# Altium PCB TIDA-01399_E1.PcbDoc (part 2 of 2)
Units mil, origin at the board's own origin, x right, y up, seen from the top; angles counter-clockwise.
Board outline 5937.01 x 6299.21 mil, 4 copper layers (Top Layer, MidLayer1, MidLayer2, Bottom Layer), stack 61.2 mil thick; 192 components, 137 nets, 411 pads, 57 vias.
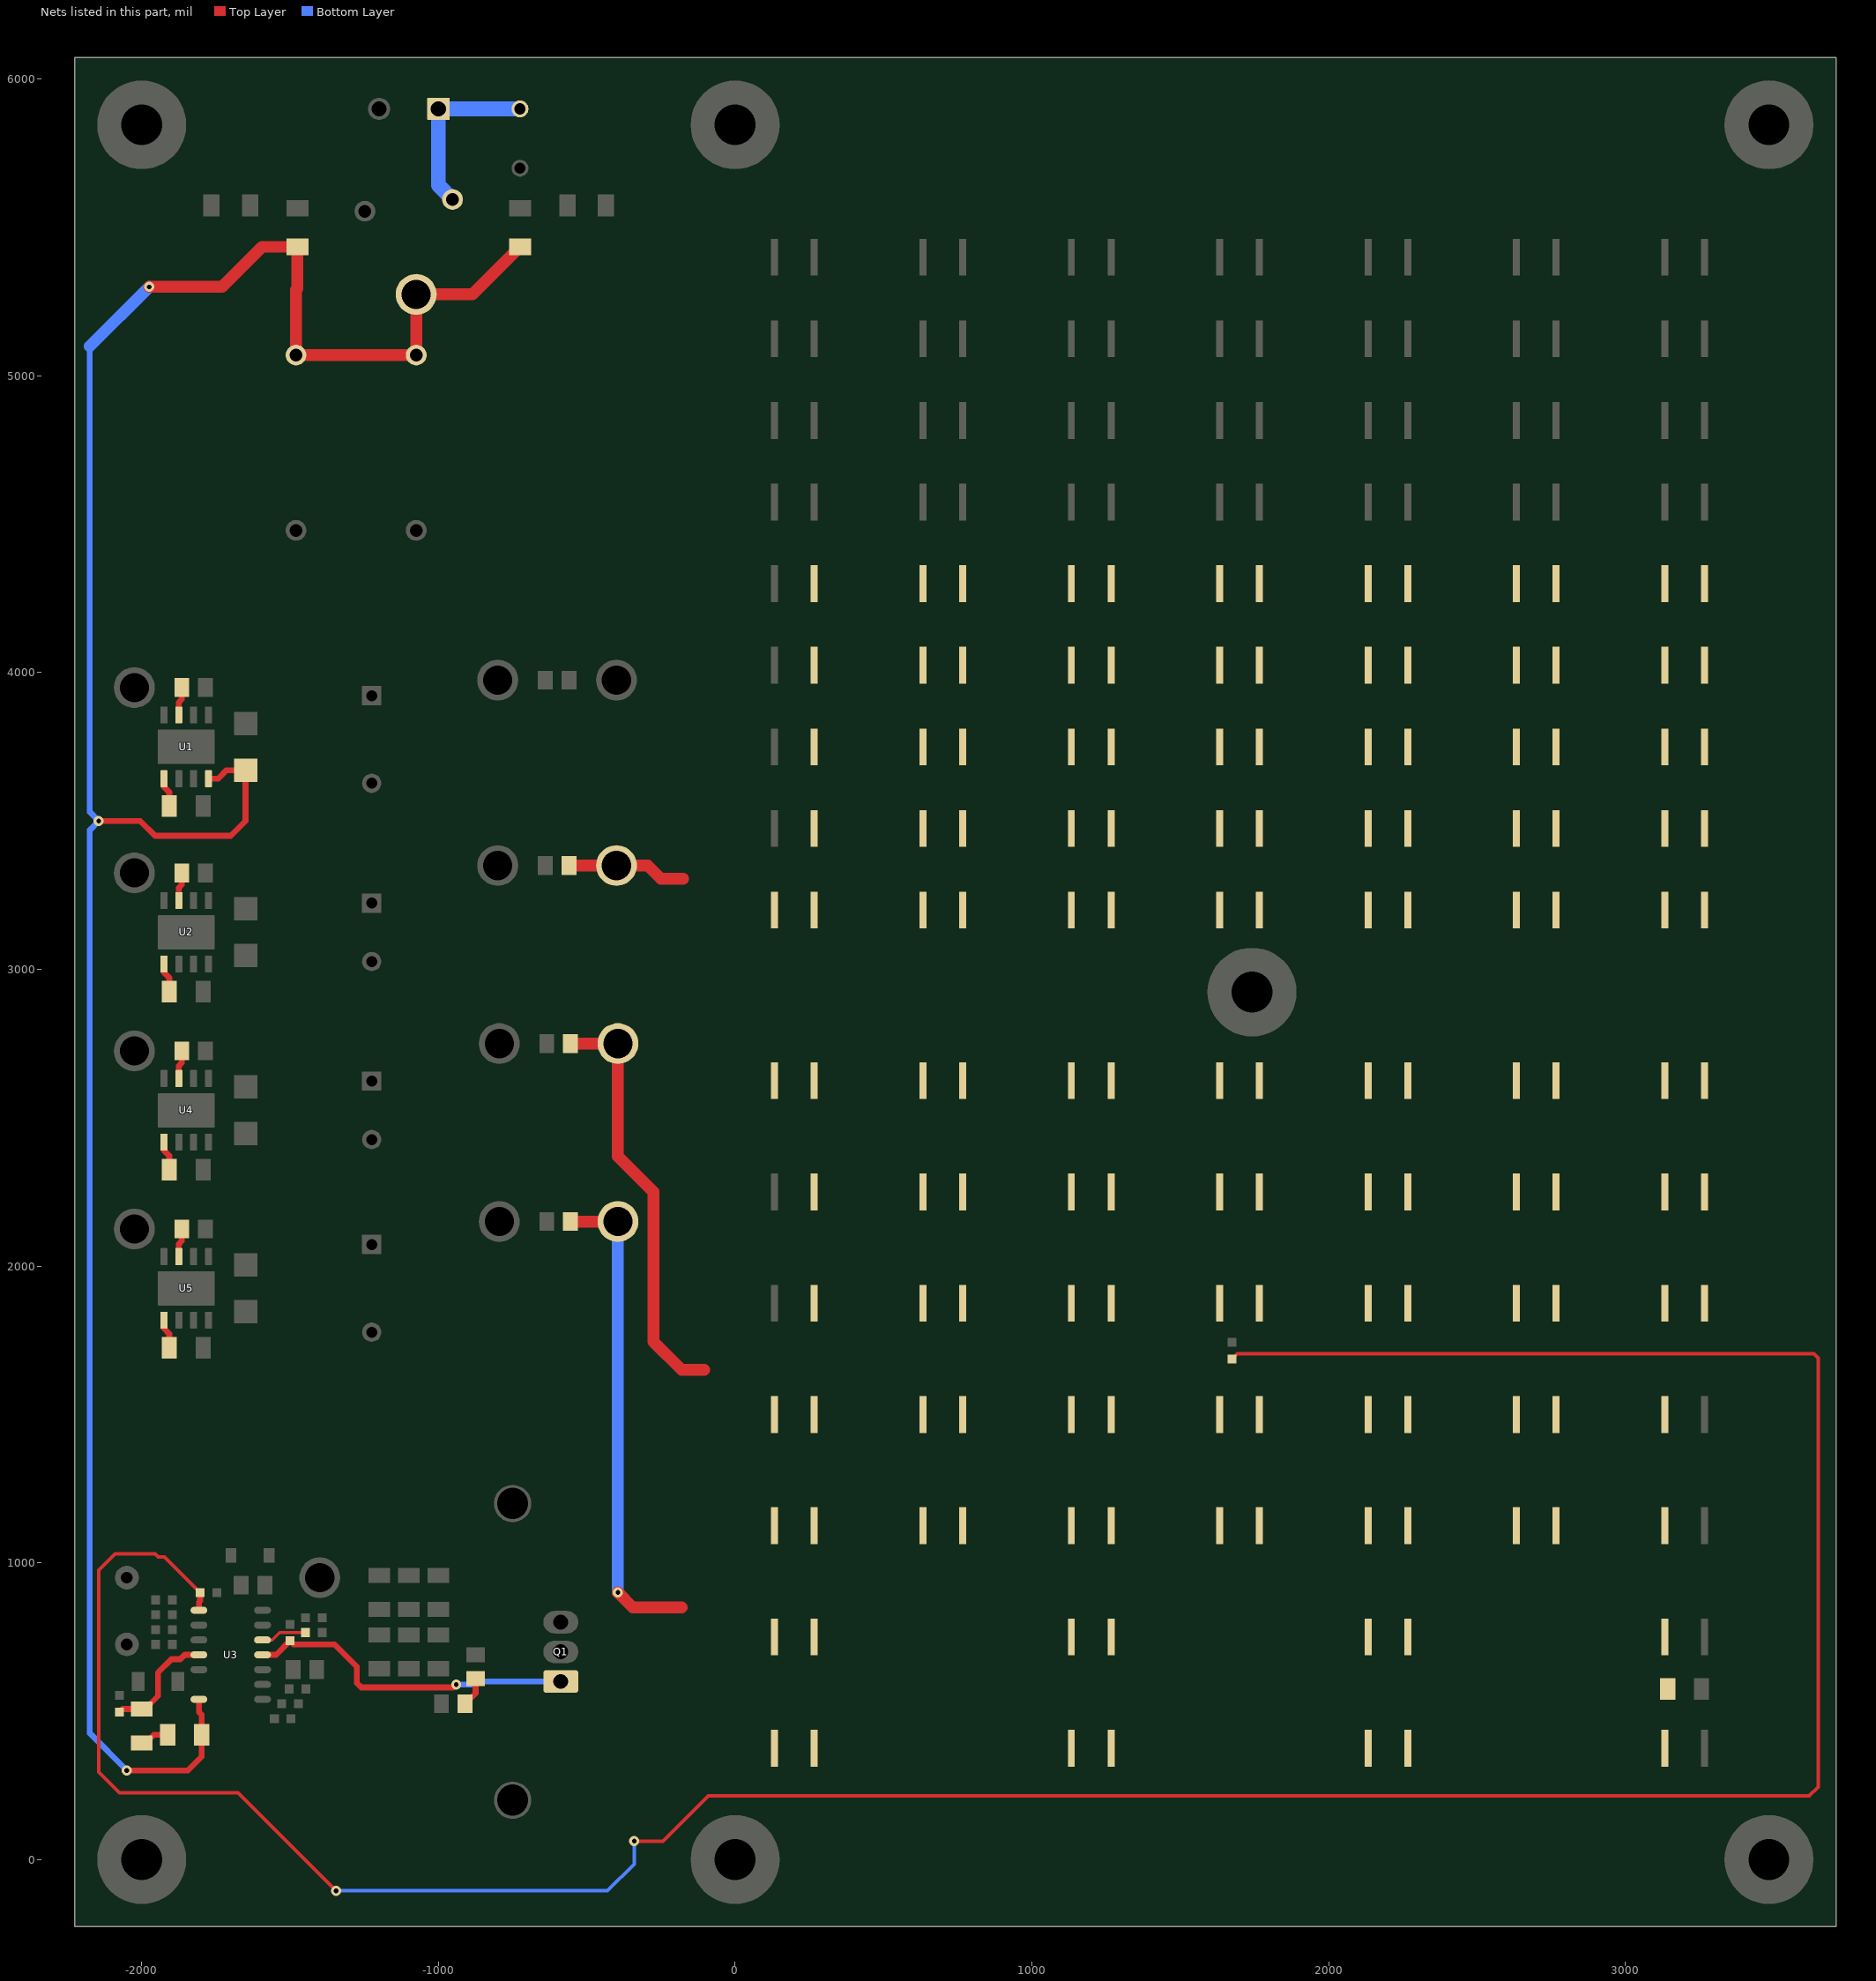
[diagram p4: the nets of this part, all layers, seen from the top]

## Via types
v1: diameter 34, hole 16, Top Layer to Bottom Layer, 25 vias
v2: diameter 19.68, hole 7.87, Top Layer to Bottom Layer, tented both sides, 16 vias
v3: diameter 19.68, hole 7.87, Top Layer to Bottom Layer, 16 vias

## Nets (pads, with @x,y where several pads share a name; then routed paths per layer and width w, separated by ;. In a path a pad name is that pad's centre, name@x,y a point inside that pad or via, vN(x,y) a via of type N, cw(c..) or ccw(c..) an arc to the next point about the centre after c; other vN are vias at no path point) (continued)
NetD32_2: D32.2 D33.1
NetD33_2: D33.2 D34.1
NetD34_2: D34.2 D35.1
NetD35_2: D35.2 D36.1
NetD36_2: D36.2 D37.1
NetD37_2: D37.2 D38.1
NetD38_2: D38.2 D61.1
NetD39_2: D39.2 D40.1
NetD40_2: D40.2 D41.1
NetD41_2: D41.2 D42.1
NetD42_2: D42.2 D43.1
NetD43_2: D43.2 D44.1
NetD44_2: D44.2 D45.1
NetD45_2: D45.2 D54.1
NetD48_1: D48.1 D49.2
NetD49_1: D49.1 D50.2
NetD50_1: D50.1 D51.2
NetD51_1: D51.1 D52.2
NetD52_1: D52.1 D53.2
NetD53_1: D53.1 D54.2
NetD55_1: D55.1 D56.2
NetD56_1: D56.1 D57.2
NetD57_1: D57.1 D58.2
NetD58_1: D58.1 D59.2
NetD59_1: D59.1 D60.2
NetD60_1: D60.1 D61.2
NetD62_1: D62.1 D70.1 R8.2 TP5.1 | length 403.6
  Top Layer w40: R8.2@-560,3350 TP5.1@-400,3350 -295,3350 -250,3305 -175,3305
NetD62_2: D62.2 D63.1
NetD63_2: D63.2 D64.1
NetD64_2: D64.2 D65.1
NetD65_2: D65.2 D66.1
NetD66_2: D66.2 D67.1
NetD67_2: D67.2 D68.1
NetD68_2: D68.2 D90.1
NetD70_2: D70.2 D71.1
NetD71_2: D71.2 D72.1
NetD72_2: D72.2 D73.1
NetD73_2: D73.2 D74.1
NetD74_2: D74.2 D75.1
NetD75_2: D75.2 D76.1
NetD76_2: D76.2 D83.1
NetD77_1: D77.1 D78.2
NetD78_1: D78.1 D79.2
NetD79_1: D79.1 D80.2
NetD80_1: D80.1 D81.2
NetD81_1: D81.1 D82.2
NetD82_1: D82.1 D83.2
NetD84_1: D84.1 D85.2
NetD85_1: D85.1 D86.2
NetD86_1: D86.1 D87.2
NetD87_1: D87.1 D88.2
NetD88_1: D88.1 D89.2
NetD89_1: D89.1 D90.2
NetD91_1: D91.1 D99.1 R17.2 TP9.1 | length 1419.1
  Top Layer w40: R17.2@-555,2750 TP9.1@-395,2750 -395,2370 -275,2250 -275,1745 -180,1650 ; -175,1650 -105,1650
NetD91_2: D91.2 D92.1
NetD92_2: D92.2 D93.1
NetD93_2: D93.2 D94.1
NetD94_2: D94.2 D95.1
NetD95_2: D95.2 D96.1
NetD96_2: D96.2 D97.1
NetD99_2: D99.2 D100.1
NetD100_2: D100.2 D101.1
NetD101_2: D101.2 D102.1
NetD102_2: D102.2 D103.1
NetD103_2: D103.2 D104.1
NetD104_2: D104.2 D105.1
NetD107_1: D107.1 D110.1 R31.2 TP14.1 | length 1645.7
  Top Layer w40: R31.2@-555,2150 TP14.1@-395,2150 ; v1(-395,900) -345,850 -180,850
  Bottom Layer w40: v1(-395,900) TP14.1@-395,2150
NetD107_2: D107.2 D108.1
NetD108_2: D108.2 D113.1
NetD110_2: D110.2 D111.1
NetD111_2: D111.2 D112.1
NetD112_2: D112.2 D113.2 D114.1 D115.1 R34.2
NetF1_2: F1.2 J1.1 RV1.2 | length 600
  Bottom Layer w50: RV1.2@-952.36,5594.69 -1000,5642.32 J1.1@-1000,5900 F1.2@-725,5900
NetQ1_1: Q1.1 R16.2 U3.4 | length 1130.2
  Top Layer w20: U3.4@-1592.72,690 -1547,690 R16.2@-1500,737 -1488,725 -1350,725 -1275,650 -1275,595 -1260,580 -950,580 v1(-940,590)
  Bottom Layer w20: v1(-940,590) -890,590 -880,600 Q1.1@-587.5,600
NetR6_1: R6.1 U1.3 | length 96.9
  Top Layer w20: U1.3@-1875,3857.28 -1875,3900 -1865,3910 R6.1@-1865,3950
NetR7_2: R7.2 U1.5 | length 100.1
  Top Layer w20: U1.5@-1925,3642.72 -1925,3615 -1907.09,3597.09 R7.2@-1907.09,3550
NetR9_1: R9.1 U2.3 | length 96.9
  Top Layer w20: U2.3@-1875,3232.28 -1875,3275 -1865,3285 R9.1@-1865,3325
NetR10_2: R10.2 R14.2 | length 99.1
  Top Layer w20: R14.2@-2000,392.91 -1987.09,392.91 -1960,420 R10.2@-1912.09,420
NetR11_2: R11.2 R12.1 | length 99.5
  Top Layer w20: R11.2@-910,525 -875,560 R12.1@-875,610
NetR13_2: R13.2 U2.5 | length 100.1
  Top Layer w20: U2.5@-1925,3017.72 -1925,2990 -1907.09,2972.09 R13.2@-1907.09,2925
NetR14_1: R14.1 R23.2 U3.11 | length 393.8
  Top Layer w20: R23.2@-2075,497 -2064.91,507.09 R14.1@-2000,507.09 -1989.17,507.09 -1945,551.26 -1945,630 -1900,675 -1870,675 -1855,690 U3.11@-1807.28,690
NetR19_1: R19.1 RT1.2 U3.8 | length 10745
  Top Layer w12: R19.1@-1803,900 -1923,1020 -1945,1020 -1955,1030 -2090,1030 -2145,975 -2145,295 -2075,225 -1675,225 v1(-1345,-105) ; v1(-340,62.27) -242.73,62.27 -90,215 3620,215 3650,245 3650,1690 3635,1705 1693,1705 RT1.2@1675,1687
  Top Layer w20: U3.8@-1807.28,840 -1807.28,867.72 -1803,872 R19.1@-1803,900
  Bottom Layer w12: v1(-1345,-105) -430,-105 -340,-15 v1(-340,62.27)
NetR21_1: R21.1 U4.3 | length 96.9
  Top Layer w20: U4.3@-1875,2632.28 -1875,2675 -1865,2685 R21.1@-1865,2725
NetR26_2: R26.2 U4.5 | length 100.1
  Top Layer w20: U4.5@-1925,2417.72 -1925,2390 -1907.09,2372.09 R26.2@-1907.09,2325
NetR28_1: R28.1 U3.5 | length 155.1
  Top Layer w10: U3.5@-1592.72,740 -1560,740 -1535,765 R28.1@-1448,765
NetR32_1: R32.1 U5.3 | length 96.9
  Top Layer w20: U5.3@-1875,2032.28 -1875,2075 -1865,2085 R32.1@-1865,2125
NetR33_2: R33.2 U5.5 | length 100.1
  Top Layer w20: U5.5@-1925,1817.72 -1925,1790 -1907.09,1772.09 R33.2@-1907.09,1725
RECT-AC: C1.1 C3.1 D8.2 D16.1 D17.1 R10.1 RECT-AC1.1 U1.8 U3.14 | length 8421.1
  Top Layer w20: v1(-2145,3500) -2005,3500 -1955,3450 -1700,3450 -1650,3500 D8.2@-1650,3671.26 -1713.74,3671.26 -1742.28,3642.72 U1.8@-1775,3642.72 ; v1(-2050,300) -1845,300 -1797.91,347.09 R10.1@-1797.91,420 -1797.91,487.91 -1807.28,497.28 U3.14@-1807.28,540
  Top Layer w40: v1(-1975,5300) -1730,5300 -1594.96,5435.04 D17.1@-1475,5435.04 -1475,5295 -1480,5290 C1.1@-1480,5070.28 C3.1@-1075,5070.28 RECT-AC1.1@-1075,5275 -885.04,5275 D16.1@-725,5435.04
  Bottom Layer w20: -2175,5100 -2175,3530 v1(-2145,3500) -2175,3470 -2175,425 v1(-2050,300)
  Bottom Layer w40: -2175,5100 v1(-1975,5300)
pads on no net: H1.1 H1.2 H2.0 U1.2 U1.6 U1.7 U1.9@-1850,3750 U2.2 U2.6 U2.7 U2.9@-1850,3125 U4.2 U4.6 U4.7 U4.9@-1850,2525 U5.2 U5.6 U5.7 U5.9@-1850,1925

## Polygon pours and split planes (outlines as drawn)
NetC14_2 on MidLayer1 "NETC14_2_L02_P000" (solid, remove dead copper, pour order 0): -2150,2250 -1500,2250 -1100,1850 -900,1650 -900,1350 -900,1150 -850,1100 -750,1000 -600,1000 -450,850 -450,550 -550,450 -850,450 -1200,800 -1200,1300 -1450,1550 -1700,1550 -2050,1550 -2150,1650
NetC12_2 on MidLayer1 "NETC12_2_L02_P002" (solid, remove dead copper, pour order 2): -2150,2850 -1100,2850 -1100,2350 -2150,2350
NetC4_2 on MidLayer1 "NETC4_2_L02_P004" (solid, remove dead copper, pour order 4): -2150,3450 -1100,3450 -1100,2950 -2150,2950
NetC2_2 on MidLayer1 "NETC2_2_L02_P006" (solid, remove dead copper, pour order 6): -2150,4100 -1100,4100 -1100,3550 -2150,3550
GND on Bottom Layer "GND_L04_P008" (solid, remove dead copper, pour order 8): -1650,6000 -350,6000 -300,6000 -300,-5 -445,-150 -1005,-150 -1405,250 -2150,250 -2150,5550 -2100,5600 -1900,5600 -1700,5800 -1700,5950

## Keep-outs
Keep-Out Layer:
  text ".Layer_Name" at -1888.75,-1283.49 h60

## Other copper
Top Layer:
  rectangle net GND: -2115,546.65 -1990,770
  rectangle net GND: -1235,895 -965,980
  rectangle net GND: -1235,620 -965,705
  rectangle net NetC7_1: -1235,735 -970,865
  rectangle net GND: -2115,675 -1940,840
  rectangle net NetD107_1: -200,250 175,870
  rectangle net NetD110_2: 225,600 1175,870
  rectangle net NetD107_2: 225,250 1175,550
  rectangle net NetD111_2: 1225,600 2175,870
  rectangle net NetD112_2: 2225,250 3175,870
  rectangle net NetD91_1: -130,1025 175,1675
  rectangle net NetD91_2: 225,1025 675,1300
  rectangle net NetD99_2: 225,1350 675,1675
  rectangle net NetD100_2: 725,1350 1175,1675
  rectangle net NetD92_2: 725,1025 1175,1300
  rectangle net NetD101_2: 1225,1350 1675,1650
  rectangle net NetD93_2: 1225,1025 1675,1300
  rectangle net NetD102_2: 1725,1350 2175,1675
  rectangle net NetD94_2: 1725,1025 2175,1300
  rectangle net NetD103_2: 2225,1350 2675,1675
  rectangle net NetD95_2: 2225,1025 2675,1300
  rectangle net NetD104_2: 2725,1350 3175,1675
  rectangle net NetD96_2: 2725,1025 3175,1300
  rectangle net NetC4_2: -200,1750 175,2425
  rectangle net NetD89_1: 2725,1750 3175,2050
  rectangle net NetD82_1: 2725,2100 3175,2425
  rectangle net NetD88_1: 2225,1750 2675,2050
  rectangle net NetD81_1: 2225,2100 2675,2425
  rectangle net NetD87_1: 1725,1750 2175,2050
  rectangle net NetD80_1: 1725,2100 2175,2425
  rectangle net NetD86_1: 1225,1775 1675,2050
  rectangle net NetD79_1: 1225,2100 1675,2425
  rectangle net NetD85_1: 725,1750 1175,2050
  rectangle net NetD78_1: 725,2100 1175,2425
  rectangle net NetD77_1: 225,2100 675,2425
  rectangle net NetD84_1: 225,1750 675,2050
  rectangle net NetD62_1: -200,2475 175,3325
  rectangle net NetD70_2: 225,2475 675,2875
  rectangle net NetD62_2: 225,2925 675,3325
  rectangle net NetD63_2: 725,2925 1175,3325
  rectangle net NetD71_2: 725,2475 1175,2875
  rectangle net NetD64_2: 1225,2925 1550,3325
  rectangle net NetD64_2: 1525,3100 1675,3325
  rectangle net NetD72_2: 1525,2475 1675,2725
  rectangle net NetD72_2: 1225,2475 1550,2875
  region net NetD65_2: 1975,3325 1725,3325 1725,3100 1975,3100
  region net NetD65_2: 2175,3325 1950,3325 1950,2925 2175,2925
  region net NetD73_2: 2175,2900 1950,2900 1950,2475 2175,2475
  region net NetD73_2: 1975,2725 1725,2725 1725,2475 1975,2475
  rectangle net NetD74_2: 2225,2475 2675,2875
  rectangle net NetD66_2: 2225,2925 2675,3325
  rectangle net NetD75_2: 2725,2475 3175,2875
  rectangle net NetD67_2: 2725,2925 3175,3325
  region net NetC14_2: 3625,935 3225,935 3225,250 3625,250
  region net NetC12_2: 3625,1670 3225,1670 3225,960 3625,960
  region net NetD76_2: 3450,2875 3225,2875 3225,2100 3450,2100
  rectangle net NetD68_2: 3225,1750 3625,2050
  rectangle net NetD68_2: 3225,2925 3625,3325
  rectangle net NetD68_2: 3475,2000 3625,2975
  rectangle net NetC2_2: -200,3375 175,3850
  rectangle net NetD55_1: 225,3375 675,3600
  rectangle net NetD48_1: 225,3625 675,3850
  rectangle net NetD49_1: 725,3625 1175,3850
  rectangle net NetD56_1: 725,3375 1175,3600
  rectangle net NetD50_1: 1225,3625 1675,3850
  rectangle net NetD57_1: 1225,3375 1675,3600
  rectangle net NetD51_1: 1725,3625 2175,3850
  rectangle net NetD58_1: 1725,3375 2175,3600
  rectangle net NetD52_1: 2225,3625 2675,3850
  rectangle net NetD59_1: 2225,3375 2675,3600
  rectangle net NetD53_1: 2725,3625 3175,3850
  rectangle net NetD60_1: 2725,3375 3175,3600
  rectangle net NetD38_2: 3225,3375 3625,3600
  rectangle net NetD38_2: 3225,4175 3625,4400
  rectangle net NetD45_2: 3225,3625 3450,4150
  rectangle net NetD38_2: 3475,3550 3625,4225
  rectangle net NetD44_2: 2725,3925 3175,4150
  rectangle net NetD37_2: 2725,4175 3175,4400
  rectangle net NetD36_2: 2225,4175 2675,4400
  rectangle net NetD43_2: 2225,3925 2675,4150
  rectangle net NetD42_2: 1725,3925 2175,4150
  rectangle net NetD35_2: 1725,4175 2175,4400
  rectangle net NetD41_2: 1225,3925 1675,4150
  rectangle net NetD34_2: 1225,4175 1675,4400
  rectangle net NetD40_2: 725,3925 1175,4150
  rectangle net NetD33_2: 725,4175 1175,4400
  rectangle net NetD39_2: 225,3925 675,4150
  rectangle net NetD32_2: 225,4175 675,4400
  region net NetD18_2: -75,4775 -200,4775 -200,4100 -75,4100
  region net NetD25_2: 175,4700 -50,4700 -50,4175 175,4175
  region net NetD18_2: 175,4950 -200,4950 -200,4725 175,4725
  region net NetD18_2: 175,4150 -200,4150 -200,3925 175,3925
  rectangle net NetD18_1: 225,4725 675,4950
  rectangle net NetD25_1: 225,4475 675,4700
  rectangle net NetD19_1: 725,4725 1175,4950
  rectangle net NetD26_1: 725,4475 1175,4700
  rectangle net NetD20_1: 1225,4725 1675,4950
  rectangle net NetD27_1: 1225,4475 1675,4700
  rectangle net NetD21_1: 1725,4725 2175,4950
  rectangle net NetD28_1: 1725,4475 2175,4700
  rectangle net NetD22_1: 2225,4725 2675,4950
  rectangle net NetD29_1: 2225,4475 2675,4700
  rectangle net NetD23_1: 2725,4725 3175,4950
  rectangle net NetD30_1: 2725,4475 3175,4700
  rectangle net NetD7_2: 3475,4650 3625,5325
  rectangle net NetD15_2: 3225,4725 3450,5250
  rectangle net NetD7_2: 3225,5275 3625,5500
  rectangle net NetD7_2: 3225,4475 3625,4700
  rectangle net NetD1_1: -200,5025 175,5500
  rectangle net NetD9_2: 225,5025 675,5250
  rectangle net NetD1_2: 225,5275 675,5500
  rectangle net NetD2_2: 725,5275 1175,5500
  rectangle net NetD10_2: 725,5025 1175,5250
  rectangle net NetD3_2: 1225,5275 1675,5500
  rectangle net NetD11_2: 1225,5025 1675,5250
  rectangle net NetD4_2: 1725,5275 2175,5500
  rectangle net NetD12_2: 1725,5025 2175,5250
  rectangle net NetD5_2: 2225,5275 2675,5500
  rectangle net NetD13_2: 2225,5025 2675,5250
  rectangle net NetD6_2: 2725,5275 3175,5500
  rectangle net NetD14_2: 2725,5025 3175,5250
  rectangle net NetD108_2: 1225,250 2175,550
  text ".Layer_Name" at -1888.75,-1283.49 h60
MidLayer1:
  region: 3650,3250 1984.25,3250 1984.25,2500 3650,2500
  rectangle: -200,2500 1500,3250
  rectangle: -200,3196.46 3650,5596.46
  rectangle: -200,250 3650,2650
  text ".Layer_Name" at -1888.75,-1283.49 h60
MidLayer2:
  region: 3650,3250 1984.25,3250 1984.25,2500 3650,2500
  rectangle: -200,2500 1500,3250
  rectangle: -200,3196.46 3650,5596.46
  rectangle: -200,250 3650,2650
  text ".Layer_Name" at -1888.75,-1283.49 h60
Bottom Layer:
  rectangle: -200,250 3650,2650
  rectangle: -200,3196.46 3650,5596.46
  rectangle: -200,2500 1500,3250
  region: 3650,3250 1984.25,3250 1984.25,2500 3650,2500
  text ".PRJ_Number" at -1325,45 h50
  text ".PCB_Rev" at -1325,-35 h50
  text ".Layer_Name" at -1888.75,-1283.49 h60

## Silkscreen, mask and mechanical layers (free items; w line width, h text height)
Top Overlay:
  lines w7: -1290,1150 -1290,1030 -1265,1005
  text "108 - 132VAC" at -825,6005 h60
  text "MADE IN USA" at 3545,880 h100 r90
  text "HIGH POWER TPS92411" at 395,60 h150
  text "'.CopyrightYear'" at 525,-95 h100
  text "©" at 412,-102.55 h125
  text ".Layer_Name" at -1888.75,-1283.49 h60
Bottom Overlay:
  text ".Layer_Name" at -1888.75,-1283.49 h60
Top Paste:
  text ".Layer_Name" at -1888.75,-1283.49 h60
Bottom Paste:
  text ".Layer_Name" at -1888.75,-1283.49 h60
Top Solder:
  text ".Layer_Name" at -1888.75,-1283.49 h60
  text ".Layer_Name" at -1888.75,-1283.49 h60
Bottom Solder:
  text ".Layer_Name" at -1888.75,-1283.49 h60
Drill Guide:
  text ".Layer_Name" at -1888.75,-1283.49 h60
M1 Board Outline:
  the board outline again, w7
  text ".Layer_Name" at -1888.75,-1283.49 h60
M2 Board Dimensions:
  text ".Layer_Name" at -1888.75,-1283.49 h60
M3 3D STEP Top:
  text ".Layer_Name" at -1888.75,-1283.49 h60
M4 3D STEP Bottom:
  text ".Layer_Name" at -1888.75,-1283.49 h60
M5 Assembly Top:
  lines w10: -2757.75,-1355.17 3842.25,-1355.17 ; -2757.75,-1151.83 3844.25,-1151.83 ; -2757.75,-948.5 -2757.75,-1558.5 1247.25,-1558.5 3844.25,-1558.5 3844.25,-948.5 -2757.25,-948.5 -2757.25,-1558.5 -1181.75,-1558.5 ; -292.75,-1558.5 -292.75,-948.5 ; 974.25,-1151.83 974.25,-948.5 ; 1814.25,-1151.83 1814.25,-948.5 ; 2436.25,-1565 2436.25,-1362.17
  text "COMPONENTS MARKED 'DNP' SHOULD NOT BE POPULATED, AND MAY NOT BE IN BILL OF MATERIALS" at -1312.25,-743.5 h60
  text "ASSEMBLY VARIANT:" at -1312.75,-859 h60
  text ".VariantName" at -276.75,-859 h60
  text "PCB VIEWED FROM TOP SIDE" at -2694.25,-1080.67 h60
  text "BOARD #:" at -217.75,-1080.67 h60
  text ".PRJ_Number" at 327.75,-1080.67 h60
  text "REV:" at 1172.25,-1080.67 h60
  text ".PCB_Rev" at 1463.75,-1080.67 h60
  text "SVN REV:" at 2010.25,-1080.67 h60
  text ".VersionControl_RevNumber" at 2516.25,-1080.67 h60
  text "IGNORE ->" at -2694.25,-1283.49 h60
  text "PLOT NAME =" at -2694.25,-1489.34 h60
  text ".plot_File_Name" at -1888.75,-1489.34 h60
  text "GENERATED    :" at -215.75,-1489.34 h60
  text ".Print_Date" at 653.75,-1489.34 h60
  text ".Print_Time" at 1382.75,-1489.34 h60
  text "TEXAS INSTRUMENTS" at 2647.25,-1489.34 h60
M6 Assembly Bottom:
  lines w10: -2758.25,-1152.33 3843.75,-1152.33 ; -2756.25,-1355.67 3843.75,-1355.67 ; -1350.25,-1565.5 -1350.25,-1362.67 ; -728.25,-1152.33 -728.25,-949 ; 111.75,-1152.33 111.75,-949 ; 1378.75,-1559 1378.75,-949 ; 2267.75,-1559 3843.25,-1559 3843.25,-949 -2758.25,-949 -2758.25,-1559 -161.25,-1559 3843.75,-1559 3843.75,-949
  text "COMPONENTS MARKED 'DNP' SHOULD NOT BE POPULATED, AND MAY NOT BE IN BILL OF MATERIALS" at 3636.25,-743 h60
  text ".VariantName" at 2592.25,-859 h60
  text "ASSEMBLY VARIANT:" at 3631.25,-859 h60
  text ".VersionControl_RevNumber" at -1430.25,-1081.17 h60
  text "SVN REV:" at -924.25,-1081.17 h60
  text ".PCB_Rev" at -377.75,-1081.17 h60
  text "REV:" at -86.25,-1081.17 h60
  text ".PRJ_Number" at 758.25,-1081.17 h60
  text "BOARD #:" at 1303.75,-1081.17 h60
  text "PCB VIEWED FROM BOTTOM SIDE" at 3780.25,-1081.17 h60
  text "IGNORE ->" at 82.1,-1283.49 h60
  text "TEXAS INSTRUMENTS" at -1561.25,-1489.84 h60
  text ".Print_Time" at -296.75,-1489.84 h60
  text ".Print_Date" at 432.25,-1489.84 h60
  text "GENERATED    :" at 1301.75,-1489.84 h60
  text ".plot_File_Name" at 2974.75,-1489.84 h60
  text "PLOT NAME =" at 3780.25,-1489.84 h60
M7 LPKF Text Top:
  lines w7: -226.38,-226.38 -226.38,6072.83 ; -226.38,5625 -226.38,210.63 3699.37,210.63 ; -226.38,5635.83 3710.63,5635.83
M9 Title Sheet:
  drawing of 57 lines, arcs and shapes, not listed
  text "1" at -1725.91,7611.5 h70
  text "2" at 769.75,7611.5 h70
  text "3" at 3259.1,7611.5 h70
  text "4" at 5765.76,7611.5 h70
  text "5" at 8264.75,7611.5 h70
  text "6" at 10769.75,7611.5 h70
  text "A" at -2882.25,6468.5 h70
  text "A" at 11917.75,6468.5 h70
  text "B" at -2882.25,4088.5 h70
  text "B" at 11917.75,4088.5 h70
  text "C" at -2882.25,1713.5 h70
  text "C" at 11917.75,1713.5 h70
  text "PROJECT TITLE:" at 8877.75,-147.5 h45
  text ".PRJ_Title" at 8927.75,-280.83 h70
  text "DESIGNED FOR:" at 8877.75,-448.5 h45
  text ".PRJ_Customer" at 8927.75,-588.5 h70
  text "D" at -2882.25,-656.5 h70
  text "D" at 11917.75,-656.5 h70
  text "FILE NAME:" at 8877.75,-748.5 h45
  text ".PCB_File_Name_No_Path" at 8927.75,-868.5 h70
  text "Texas Instruments (TI) and/or its licensors do not warrant the accuracy or completeness of this specification" at 3908.25,-1030.34 h45
  text "ENGINEER:" at 8877.75,-1038.5 h45
  text "LAYOUT BY:" at 10382.75,-1038.5 h45
  text "or any information contained therein. TI and/or its licensors do not warrant that this design will meet" at 3863.27,-1143 h45
  text ".PRJ_Engineer" at 8927.75,-1193.49 h70
  text ".PCB_Layout" at 10433.25,-1193.49 h70
  text "the specifications, will be suitable for your application or fit for any particular purpose, or will operate in" at 3863.27,-1255.67 h45
  text ".Layer_Name" at -1888.75,-1283.49 h60
  text "ALTIUM DESIGNER VERSION:" at 10382.75,-1348.5 h45
  text "an implementation. TI and/or its licensors do not warrant that the design is production worthy. You should" at 3863.27,-1368.33 h45
  text "completely validate and test your design implementation to confirm the system functionality for your application." at 3908.25,-1481 h45
  text ".print_Scale" at 8927.75,-1481.83 h70
  text ".Application_BuildNumber" at 10433.25,-1481.83 h70
  text "1" at -1725.91,-1688.5 h70
  text "2" at 769.75,-1688.5 h70
  text "3" at 3259.1,-1688.5 h70
  text "4" at 5765.76,-1688.5 h70
  text "5" at 8264.75,-1688.5 h70
  text "6" at 10769.75,-1688.5 h70
M10 Fab Notes:
  drawing of 203 lines, arcs and shapes, not listed
  text "DESIGN INFORMATION" at 9915.27,6385 h60
  text "(REFER ALSO ARRAY/PANEL PROFILING INFORMATION)" at 9553.71,6223.29 h60
  text "BOARD SIZE" at 8867.71,6219 h60
  text "5937MIL" at 9330.03,6091.18 h60
  text "X" at 9835.71,6091.18 h60
  text "6299MIL" at 10067.03,6091.18 h60
  text "Number of Layers :" at 9270.71,5894 h60
  text "4" at 10365.52,5884 h60
  text "MIN. TRACK WIDTH:" at 9270.71,5755 h60
  text "MIL" at 10521.71,5755 h60
  text "10" at 10334.25,5750 h60
  text "MIN. CLEARANCE:" at 9270.71,5623 h60
  text "8" at 10366.95,5623 h60
  text "MIL" at 10521.71,5623 h60
  text "MIN. VIA PAD SIZE:" at 9270.71,5491 h60
  text "34" at 10336.96,5491 h60
  text "MIL" at 10521.71,5491 h60
  text "0.05mm (2MIL)" at 9965.71,5349.29 h60
  text "MINIMUM ANNULAR RING" at 8941.48,5345 h60
  text "EXTERNAL" at 10673.71,5345 h60
  text "PER" at 9141.48,5227 h60
  text "IPC-D-275 CLASS 2 LEVEL C" at 9361.48,5227 h60
  text "MIL, HOLES" at 10849.71,5114.71 h60
  text "+/-" at 10457.25,5114 h60
  text "+/-" at 11311.25,5114 h60
  text "REGISTRATION TOLERANCES:" at 8941.48,5109 h60
  text "METAL" at 10141.25,5109 h60
  text "5" at 10717.45,5109 h60
  text "3" at 11550.45,5109 h60
  text "MIL" at 11666.71,5109 h60
  text "MATERIAL:" at 8866.71,4899.54 h60
  text "FR-4 High Tg" at 9853.15,4759.21 h60
  text "FR-4" at 9327.71,4750.64 h60
  text "OTHER" at 10775.71,4750.64 h60
  text "X" at 9139.25,4750 h60
  text "62 MIL (1.6mm) +/-10%" at 9607.81,4587.92 h60
  text "THICKNESS:" at 8941.48,4583.64 h60
  text "OTHER" at 10892.71,4583.64 h60
  text "X" at 9470,4575 h60
  text "TOLERANCE:" at 8941.48,4425.64 h60
  text "X" at 9780.79,4425.64 h60
  text "ANSI IPC-6012 TYPE 3 CLASS 2" at 9967.73,4425.64 h60
  text "OTHER +/-" at 9967.71,4269.64 h60
  text "BOW & TWIST:" at 8941.48,4112.64 h60
  text "X" at 9780.79,4112.64 h60
  text "ANSI IPC-6012 TYPE 3 CLASS 2" at 9967.73,4112.64 h60
  text "OTHER +/-" at 9967.71,3954.13 h60
  text "COPPER THICKNESS (FINISHED):" at 8866.71,3818.64 h60
  text "1.4MIL (1oz)" at 9746.71,3665.92 h60
  text "2MIL (1.4oz)" at 10513.71,3665.92 h60
  text "2.8MIL (2oz)" at 11240.71,3665.92 h60
  text "OUTER:" at 9223.71,3661.64 h60
  text "X" at 9625,3650 h60
  text "1.4MIL (1oz)" at 10096.71,3508.92 h60
  text "2.8MIL (2oz)" at 10940.71,3508.92 h60
  text "INNER SIGNAL:" at 9223.71,3504.64 h60
  text "X" at 9965,3490 h60
  text "DRILLING:" at 8866.71,3365.64 h60
  text "REFERENCE:" at 8941.48,3248.64 h60
  text "X" at 9589.71,3248.64 h60
  text "AS SHOWN" at 9776.71,3248.64 h60
  text "X" at 10490.71,3248.64 h60
  text "NC_DRILL FILES" at 10627.71,3248.64 h60
  text "PTH MIN COPPER THICKNESS:" at 8941.48,3090.64 h60
  text "X" at 10291.71,3090.64 h60
  text "1MIL" at 10428.71,3090.64 h60
  text "OTHER" at 10925.71,3090.64 h60
  text "BOARD FINISH:" at 8866.71,2931.64 h60
  text "SILKSCREEN:" at 9021.93,2813.64 h60
  text "X" at 9970.71,2813.64 h60
  text "TOP" at 10096.71,2813.64 h60
  text "BOTTOM" at 10607.71,2813.64 h60
  text "X" at 9959.25,2650 h60
  text "SILKSCREEN COLOR:" at 9021.93,2646.64 h60
  text "WHITE" at 10096.71,2646.64 h60
  text "OTHER" at 10607.71,2646.64 h60
  text "SOLDER RESIST COLOR:" at 9021.93,2476.64 h60
  text "X" at 9584.25,2325 h60
  text "GREEN" at 9716.71,2317.44 h60
  text "BLUE" at 10307.71,2317.44 h60
  text "OTHER" at 10845.71,2317.44 h60
  text "IMMERSION GOLD (ENIG)" at 9927.71,2128.92 h60
  text "SURFACE FINISH:" at 8866.71,2124.64 h60
  text "Pb-FREE HASL" at 11160.01,2124.64 h60
  text "HASL" at 10360.67,1981.64 h60
  text "X" at 9750,1975 h60
  text "OTHER" at 9927.71,1967.64 h60
  text "X" at 9750,1796 h60
  text "ARRAY/PANEL:" at 8866.71,1788.64 h60
  text "CUT AND TRIM PER MECH LAYER 1" at 9927.71,1784.35 h60
  text "N.C. ROUTE" at 9927.71,1632.64 h60
  text "V. SCORE" at 10793.71,1632.64 h60
  text "CERTIFICATION:" at 8866.71,1495.64 h60
  text "MATERIALS AND WORKMANSHIP FOR ALL PCBS" at 9591.71,1495.64 h60
  text "TO MEET OR EXCEED THE REQUIREMENTS OF:" at 9591.71,1397.64 h60
  text "X" at 9218.22,1261.13 h60
  text "ANSI IPC-A-600F CLASS ->" at 9357.21,1261.13 h60
  text "X" at 10996.27,1261.13 h60
  text "2" at 11115.22,1261.14 h60
  text "1" at 10800.22,1259.64 h60
  text "3" at 11469.22,1259.64 h60
  text "X" at 9220.27,1101.64 h60
  text "UL 94V-0" at 9357.22,1101.64 h60
  text "RoHS" at 10169.22,1101.64 h60
  text "OTHER" at 10813.62,1101.64 h60
  text "ADDITIONAL REQUIREMENTS:" at 8866.71,960.64 h60
  text "MICROSECTION:" at 8941.48,845.64 h60
  text "YES" at 9847.22,845.64 h60
  text "REQUIRED" at 10708.71,689.49 h60
  text "BARE BOARD ELEC. TEST:" at 8941.48,686.64 h60
  text "NONE" at 10247.22,686.64 h60
  text "PER ORDER" at 11300.71,686.64 h60
  text "X" at 10124.25,680 h60
  text "MANUFACTURER'S ID/LOGO:" at 8941.48,529.64 h60
  text "RAIL" at 10407.22,525.35 h60
  text "X" at 10784.25,525 h60
  text "METAL" at 10899.03,525.35 h60
  text "SILK" at 11410.71,525.35 h60
  text ".Layer_Name" at -1888.75,-1283.49 h60
M11 Gerber Information:
  lines w10: -2757.75,-1355.17 3842.25,-1355.17 ; -2757.75,-1151.83 3844.25,-1151.83 ; -2757.75,-948.5 -2757.75,-1558.5 1247.25,-1558.5 3844.25,-1558.5 3844.25,-948.5 -2757.25,-948.5 -2757.25,-1558.5 -1181.75,-1558.5 ; -292.75,-1558.5 -292.75,-948.5 ; 974.25,-1151.83 974.25,-948.5 ; 1814.25,-1151.83 1814.25,-948.5 ; 2436.25,-1565 2436.25,-1362.17
  text "ALL ARTWORK VIEWED FROM TOP SIDE" at -2694.25,-1080.67 h60
  text "BOARD #:" at -217.75,-1080.67 h60
  text ".PRJ_Number" at 327.75,-1080.67 h60
  text "REV:" at 1172.25,-1080.67 h60
  text ".PCB_Rev" at 1463.75,-1080.67 h60
  text "SVN REV:" at 2010.25,-1080.67 h60
  text ".VersionControl_RevNumber" at 2516.25,-1080.67 h60
  text "LAYER NAME =" at -2694.25,-1283.49 h60
  text "PLOT NAME =" at -2694.25,-1489.34 h60
  text ".plot_File_Name" at -1888.75,-1489.34 h60
  text "GENERATED    :" at -215.75,-1489.34 h60
  text ".Print_Date" at 653.75,-1489.34 h60
  text ".Print_Time" at 1382.75,-1489.34 h60
  text "TEXAS INSTRUMENTS" at 2647.25,-1489.34 h60
M12 Stackup:
  drawing of 295 lines, arcs and shapes, not listed
  text "Layer" at 4142.5,7327.5 h60
  text "Name" at 4552.41,7327.5 h60
  text "Material" at 5482.16,7327.5 h60
  text "Thickness" at 6341.92,7327.5 h60
  text "Constant" at 6991.76,7327.5 h60
  text "Board Layer Stack" at 7561.62,7327.5 h60
  text "1" at 4142.5,7207.5 h60
  text "Top Overlay" at 4552.41,7207.5 h60
  text "2" at 4142.5,7087.5 h60
  text "Top Solder" at 4552.41,7087.5 h60
  text "Solder Resist" at 5482.16,7087.5 h60
  text "0.40mil" at 6341.92,7087.5 h60
  text "3.5" at 6991.76,7087.5 h60
  text "3" at 4142.5,6967.5 h60
  text "Top Layer" at 4552.41,6967.5 h60
  text "Copper" at 5482.16,6967.5 h60
  text "1.40mil" at 6341.92,6967.5 h60
  text "4" at 4142.5,6847.5 h60
  text "Dielectric1" at 4552.41,6847.5 h60
  text "FR-4" at 5482.16,6847.5 h60
  text "8.00mil" at 6341.92,6847.5 h60
  text "4.8" at 6991.76,6847.5 h60
  text "5" at 4142.5,6727.5 h60
  text "MidLayer1" at 4552.41,6727.5 h60
  text "Copper" at 5482.16,6727.5 h60
  text "1.40mil" at 6341.92,6727.5 h60
  text "6" at 4142.5,6607.5 h60
  text "Dielectric2" at 4552.41,6607.5 h60
  text "FR-4" at 5482.16,6607.5 h60
  text "39.60mil" at 6341.92,6607.5 h60
  text "4.8" at 6991.76,6607.5 h60
  text "7" at 4142.5,6487.5 h60
  text "MidLayer2" at 4552.41,6487.5 h60
  text "Copper" at 5482.16,6487.5 h60
  text "1.40mil" at 6341.92,6487.5 h60
  text "8" at 4142.5,6367.5 h60
  text "Dielectric3" at 4552.41,6367.5 h60
  text "FR-4" at 5482.16,6367.5 h60
  text "8.00mil" at 6341.92,6367.5 h60
  text "4.8" at 6991.76,6367.5 h60
  text "9" at 4142.5,6247.5 h60
  text "Bottom Layer" at 4552.41,6247.5 h60
  text "Copper" at 5482.16,6247.5 h60
  text "1.40mil" at 6341.92,6247.5 h60
  text "10" at 4142.5,6127.5 h60
  text "Bottom Solder" at 4552.41,6127.5 h60
  text "Solder Resist" at 5482.16,6127.5 h60
  text "0.40mil" at 6341.92,6127.5 h60
  text "3.5" at 6991.76,6127.5 h60
  text "11" at 4142.5,6007.5 h60
  text "Bottom Overlay" at 4552.41,6007.5 h60
  text ".Layer_Name" at -1888.75,-1283.49 h60
M13 Component Bodies Top:
  text ".Layer_Name" at -1888.75,-1283.49 h60
M14 Component Bodies Bottom:
  text ".Layer_Name" at -1888.75,-1283.49 h60
M15 Courtyards Top:
  text ".Layer_Name" at -1888.75,-1283.49 h60
M16 Courtyards Bottom:
  text ".Layer_Name" at -1888.75,-1283.49 h60
Drill Drawing:
  drawing of 167 lines, arcs and shapes, not listed
  text "Symbol" at 4435.7,2492.85 h72
  text "Quantity" at 4736.36,2492.85 h72
  text "Finished Hole Size" at 5068.52,2492.85 h72
  text "Plated" at 5705,2492.85 h72
  text "Hole Type" at 5964.2,2492.85 h72
  text "Drill Layer Pair" at 6339.44,2492.85 h72
  text "Hole Tolerance" at 7063.99,2492.85 h72
  text "7" at 4736.36,2368.35 h60
  text "137.80mil (3.500mm)" at 5068.52,2368.35 h60
  text "NPTH" at 5705,2368.35 h60
  text "Round" at 5964.2,2368.35 h60
  text "Top Layer - Bottom Layer" at 6339.44,2368.35 h60
  text "32" at 4736.36,2243.85 h60
  text "7.87mil (0.200mm)" at 5068.52,2243.85 h60
  text "PTH" at 5705,2243.85 h60
  text "Round" at 5964.2,2243.85 h60
  text "Top Layer - Bottom Layer" at 6339.44,2243.85 h60
  text "25" at 4736.36,2119.35 h60
  text "16.00mil (0.406mm)" at 5068.52,2119.35 h60
  text "PTH" at 5705,2119.35 h60
  text "Round" at 5964.2,2119.35 h60
  text "Top Layer - Bottom Layer" at 6339.44,2119.35 h60
  text "8" at 4736.36,1994.85 h60
  text "37.00mil (0.940mm)" at 5068.52,1994.85 h60
  text "PTH" at 5705,1994.85 h60
  text "Round" at 5964.2,1994.85 h60
  text "Top Layer - Bottom Layer" at 6339.44,1994.85 h60
  text "2" at 4736.36,1870.35 h60
  text "37.40mil (0.950mm)" at 5068.52,1870.35 h60
  text "PTH" at 5705,1870.35 h60
  text "Round" at 5964.2,1870.35 h60
  text "Top Layer - Bottom Layer" at 6339.44,1870.35 h60
  text "2" at 4736.36,1745.85 h60
  text "40.00mil (1.016mm)" at 5068.52,1745.85 h60
  text "PTH" at 5705,1745.85 h60
  text "Round" at 5964.2,1745.85 h60
  text "Top Layer - Bottom Layer" at 6339.44,1745.85 h60
  text "6" at 4736.36,1621.35 h60
  text "43.00mil (1.092mm)" at 5068.52,1621.35 h60
  text "PTH" at 5705,1621.35 h60
  text "Round" at 5964.2,1621.35 h60
  text "Top Layer - Bottom Layer" at 6339.44,1621.35 h60
  text "3" at 4736.36,1496.85 h60
  text "50.00mil (1.270mm)" at 5068.52,1496.85 h60
  text "PTH" at 5705,1496.85 h60
  text "Round" at 5964.2,1496.85 h60
  text "Top Layer - Bottom Layer" at 6339.44,1496.85 h60
  text "2" at 4736.36,1372.35 h60
  text "51.18mil (1.300mm)" at 5068.52,1372.35 h60
  text "PTH" at 5705,1372.35 h60
  text "Round" at 5964.2,1372.35 h60
  text "Top Layer - Bottom Layer" at 6339.44,1372.35 h60
  text "14" at 4736.36,1247.85 h60
  text "98.43mil (2.500mm)" at 5068.52,1247.85 h60
  text "PTH" at 5705,1247.85 h60
  text "Round" at 5964.2,1247.85 h60
  text "Top Layer - Bottom Layer" at 6339.44,1247.85 h60
  text "2" at 4736.36,1123.35 h60
  text "105.12mil (2.670mm)" at 5068.52,1123.35 h60
  text "PTH" at 5705,1123.35 h60
  text "Round" at 5964.2,1123.35 h60
  text "Top Layer - Bottom Layer" at 6339.44,1123.35 h60
  text "103 Total" at 4736.36,998.85 h60
  text ".Layer_Name" at -1888.75,-1283.49 h60

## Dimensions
0,0 to 1742.13,2923.23 on M2 Board Dimensions
-2000,0 to 1742.13,2923.23 on M2 Board Dimensions
-2000,0 to -2226.38,6072.83 on M2 Board Dimensions
-2000,0 to -2000,5846.46 on M2 Board Dimensions
-2000,0 to -2226.38,-226.38 on M2 Board Dimensions
0,0 to 3710.63,-226.38 on M2 Board Dimensions
0,0 to 3484.25,0 on M2 Board Dimensions
0,0 to -2000,0 on M2 Board Dimensions
0,0 to -2226.38,-226.38 on M2 Board Dimensions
